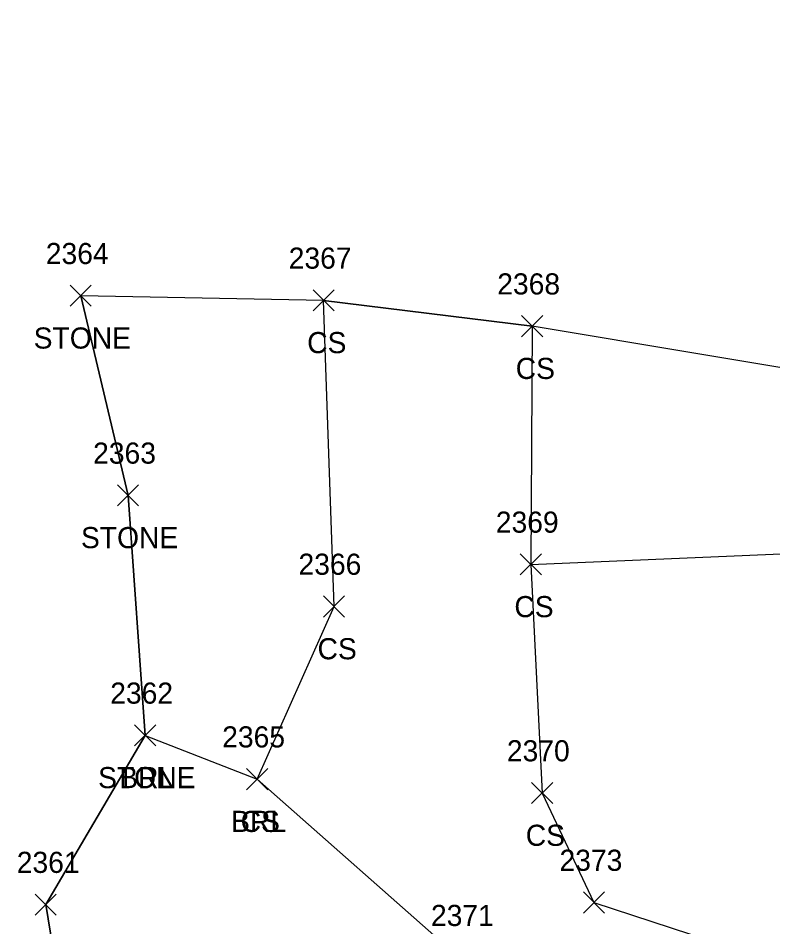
# Model space of a CAD drawing. Extents: x 1472022 to 1479249, y 777216 to 786527.
# Drawn here: x 1473551 to 1473622.4, y 779798.8 to 779884.8 of the extents above; entities that cross this region are included whole.
import ezdxf

# ---------------------------------------------------------------- set-up
doc = ezdxf.new("R2010")
doc.units = 0
for name, color, linetype in [('L_A', 7, 'Continuous'), ('L_I', 7, 'Continuous'), ('L_TIC', 7, 'Continuous'), ('LABL', 7, 'Continuous'), ('LASF', 7, 'Continuous'), ('LELB', 7, 'Continuous'), ('LSOGP', 7, 'Continuous')]:
    doc.layers.add(name, color=color, linetype=linetype)

msp = doc.modelspace()

# ---------------------------------------------------------------- linework, layer by layer
at = {"layer": 'L_TIC'}
for points in [[(1473555.927, 779857.568), (1473557.927, 779859.568)], [(1473557.927, 779857.568), (1473555.927, 779859.568)], [(1473578.919, 779857.134), (1473580.919, 779859.134)], [(1473580.919, 779857.134), (1473578.919, 779859.134)], [(1473598.661, 779854.69), (1473600.661, 779856.69)], [(1473600.661, 779854.69), (1473598.661, 779856.69)], [(1473560.404, 779838.673), (1473562.404, 779840.673)], [(1473562.404, 779838.673), (1473560.404, 779840.673)], [(1473598.533, 779832.138), (1473600.533, 779834.138)], [(1473600.533, 779832.138), (1473598.533, 779834.138)], [(1473598.533, 779832.138), (1473600.533, 779834.138)], [(1473600.533, 779832.138), (1473598.533, 779834.138)], [(1473579.902, 779828.154), (1473581.902, 779830.154)], [(1473581.902, 779828.154), (1473579.902, 779830.154)], [(1473562.025, 779815.952), (1473564.025, 779817.952)], [(1473564.025, 779815.952), (1473562.025, 779817.952)], [(1473562.025, 779815.952), (1473564.025, 779817.952)], [(1473564.025, 779815.952), (1473562.025, 779817.952)], [(1473572.624, 779811.808), (1473574.624, 779813.808)], [(1473574.624, 779811.808), (1473572.624, 779813.808)], [(1473572.624, 779811.808), (1473574.624, 779813.808)], [(1473574.624, 779811.808), (1473572.624, 779813.808)], [(1473599.612, 779810.492), (1473601.612, 779812.492)], [(1473601.612, 779810.492), (1473599.612, 779812.492)], [(1473604.508, 779800.126), (1473606.508, 779802.126)], [(1473606.508, 779800.126), (1473604.508, 779802.126)], [(1473552.61, 779799.93), (1473554.61, 779801.93)], [(1473554.61, 779799.93), (1473552.61, 779801.93)]]:
    msp.add_lwpolyline(points, dxfattribs=at)
at = {"layer": 'LABL'}
msp.add_lwpolyline([(1473563.025, 779816.952), (1473573.624, 779812.808), (1473592.772, 779795.903), (1473602.057, 779784.801), (1473625.087, 779772.145), (1473632.96, 779792.128), (1473633.457, 779807.013), (1473632.383, 779820.759), (1473631.377, 779834.479), (1473631.968, 779850.307)], dxfattribs=at)
at = {"layer": 'LASF'}
msp.add_lwpolyline([(1473556.198, 779785.034), (1473553.61, 779800.93), (1473563.025, 779816.952), (1473561.404, 779839.673), (1473556.927, 779858.568)], dxfattribs=at)
at = {"layer": 'LELB'}
for points in [[(1473573.624, 779812.808), (1473580.902, 779829.154), (1473579.919, 779858.134), (1473599.661, 779855.69), (1473599.533, 779833.138), (1473600.612, 779811.492), (1473605.508, 779801.126), (1473632.96, 779792.128)], [(1473599.533, 779833.138), (1473631.377, 779834.479), (1473641.329, 779841.478), (1473645.273, 779843.637), (1473644.729, 779850.195)]]:
    msp.add_lwpolyline(points, dxfattribs=at)
at = {"layer": 'LSOGP'}
msp.add_lwpolyline([(1473656.072, 779888.846), (1473655.033, 779881.108), (1473653.993, 779873.371), (1473644.063, 779865.462), (1473631.968, 779850.307), (1473599.661, 779855.69), (1473579.919, 779858.134), (1473556.927, 779858.568), (1473561.404, 779839.673), (1473563.025, 779816.952), (1473553.61, 779800.93), (1473556.198, 779785.034)], dxfattribs=at)

# ---------------------------------------------------------------- texts
at = {"layer": 'L_A'}
for s, p in [('STONE', (1473552.47, 779853.568)), ('CS', (1473578.36, 779853.134)), ('CS', (1473598.102, 779850.69)), ('STONE', (1473556.948, 779834.673)), ('CS', (1473597.974, 779828.138)), ('CS', (1473597.974, 779828.138)), ('CS', (1473579.343, 779824.154)), ('STONE', (1473558.568, 779811.952)), ('BRL', (1473560.568, 779811.952)), ('BRL', (1473571.167, 779807.808)), ('CS', (1473572.065, 779807.808)), ('CS', (1473599.053, 779806.492))]:
    msp.add_text(s, height=2, dxfattribs=at).set_placement(p)
at = {"layer": 'L_I'}
for s, p in [('2364', (1473553.62, 779861.568)), ('2367', (1473576.612, 779861.134)), ('2368', (1473596.354, 779858.69)), ('2363', (1473558.097, 779842.673)), ('2369', (1473596.218, 779836.138)), ('2369', (1473596.218, 779836.138)), ('2366', (1473577.54, 779832.154)), ('2362', (1473559.718, 779819.952)), ('2362', (1473559.718, 779819.952)), ('2365', (1473570.317, 779815.808)), ('2365', (1473570.317, 779815.808)), ('2370', (1473597.265, 779814.492)), ('2361', (1473550.87, 779803.93)), ('2373', (1473602.248, 779804.126)), ('2371', (1473590.079, 779798.903))]:
    msp.add_text(s, height=2, dxfattribs=at).set_placement(p)

doc.saveas('drawing.dxf')
